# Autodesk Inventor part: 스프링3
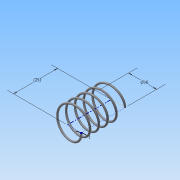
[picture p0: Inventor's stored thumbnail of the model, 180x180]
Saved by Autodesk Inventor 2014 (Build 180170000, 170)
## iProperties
Created: 2015-06
Part Number: 스프링3
Material: 강철, 연강
Document SubType Name: Modeling
Designer: Administrator
Density: 7.86 g/cm^3
Appearance: 강철
Mass: 1.53479 g
Surface Area: 7.89194 cm^2
Volume: 0.195266 cm^3
Author: Administrator
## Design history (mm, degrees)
sketch "스케치1"
  geometry: L1 (0, 0)-(8, 0); L2 (8, 0)-(8, 21.5); L3 (8, 21.5)-(0, 21.5); L4 (0, 21.5)-(0, 0); C1 r 0.5 at (8, 0)
  constraints: 8 end point, 2 parallel, 1 centre point, 1 coincident, 1 horizontal, 1 perpendicular
  dimensions: "d0" = 21.5 distance of L3.end L1.start (derived); "d1" = 16 diameter of L2 L4; "d2" = 1 diameter of C1
feature "코일1" sketch "스케치1" pitch "d3" = 10; turns "d5" = 5; dims "d4" = 21.5 (= d0), "d6" = 0, angle "d7" = 90 deg, angle "d8" = 90 deg, "d9" = 0, "d10" = 0
sketch "스케치2"
  geometry: L1 (-8.5, 0)-(-7.5, 0) reference; 1 further point
  constraints: 1 horizontal alignment
extrude "돌출1" cut sketch "스케치2" distance "d11" = 10; taper "d12" = 0 deg
node "작업 평면1"
sketch "스케치3"
  geometry: L1 (-7.5, 0)-(-8.5, 0) reference; 1 further point
  constraints: 1 horizontal alignment
extrude "돌출2" cut sketch "스케치3" distance "d14" = 10; taper "d15" = 0 deg
node "솔리드1"
node "절단 모서리 투영1"
node "절단 모서리 투영2"
other parameters: "d13" = 21.5 (= d0)
